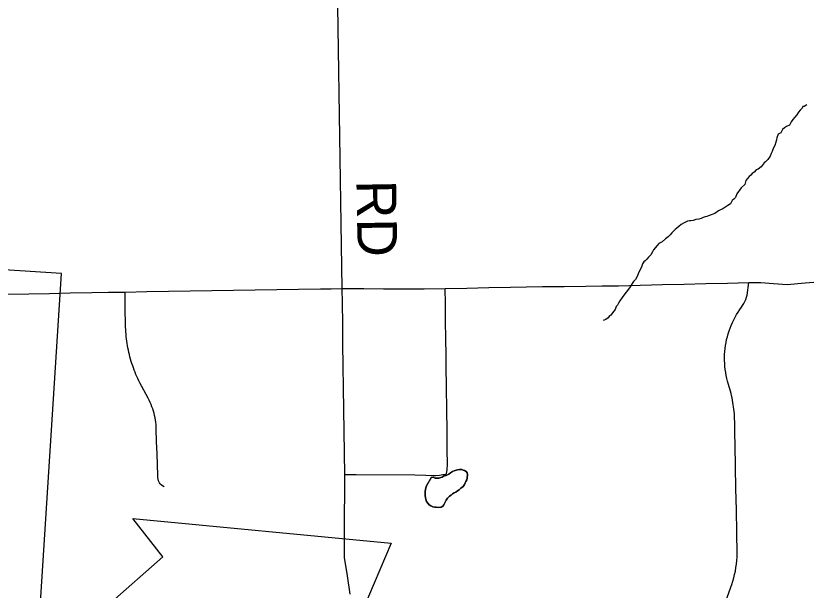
# Model space of a CAD drawing. Extents: x -11.4 to 84.1, y 11.1 to 59.
# Drawn here: x 29.384 to 30.516, y 44.72 to 45.542 of the extents above; entities that cross this region are included whole.
import ezdxf

# ---------------------------------------------------------------- set-up
doc = ezdxf.new("R2010")
doc.units = 0
for name, color, linetype in [('GM_X_Corporation', 7, 'Continuous'), ('GM_X_Minor_Lake', 7, 'Continuous'), ('GM_X_Minor_River', 7, 'Continuous'), ('GM_X_Township_Road', 7, 'Continuous'), ('GM_X_Township_Road_Text', 7, 'Continuous')]:
    doc.layers.add(name, color=color, linetype=linetype)

msp = doc.modelspace()

# ---------------------------------------------------------------- linework, layer by layer
at = {"layer": 'GM_X_Corporation'}
for points in [[(29.4173, 44.6657), (29.4494, 45.1735), (28.9418, 45.206), (28.9363, 45.0881), (28.8122, 45.094), (28.8061, 44.8928), (28.7167, 44.8942), (28.7171, 44.5971)], [(29.441, 44.6327), (29.5946, 44.7683), (29.5515, 44.8229), (29.9217, 44.7877), (29.8078, 44.5206)]]:
    msp.add_lwpolyline(points, dxfattribs=at)
at = {"layer": 'GM_X_Minor_Lake'}
for points in [[(29.9792, 44.8819), (29.9794, 44.8819), (29.9824, 44.8816), (29.9847, 44.8809), (29.9866, 44.8809), (29.9897, 44.8806), (29.9927, 44.8818), (29.9946, 44.8822), (29.9976, 44.8838), (30.0002, 44.8846), (30.004, 44.8865), (30.0066, 44.8881), (30.0093, 44.89), (30.0119, 44.8912), (30.0145, 44.892), (30.0164, 44.8928), (30.0195, 44.8933), (30.0225, 44.8929), (30.0244, 44.8922), (30.0263, 44.8915), (30.029, 44.8904), (30.0302, 44.8885), (30.031, 44.8858), (30.0303, 44.8805), (30.0296, 44.8782), (30.0285, 44.8759), (30.0274, 44.874), (30.0263, 44.8717), (30.0244, 44.8686), (30.0214, 44.8663), (30.0188, 44.864), (30.0166, 44.8624), (30.0139, 44.8608), (30.0117, 44.8597), (30.0094, 44.8581), (30.0072, 44.8565), (30.0049, 44.855), (30.0023, 44.8519), (30.0001, 44.8492), (29.9986, 44.8465), (29.9979, 44.8446), (29.9968, 44.8427), (29.9953, 44.8408), (29.993, 44.8392), (29.9888, 44.8388), (29.9858, 44.8391), (29.9839, 44.8394), (29.9812, 44.8398), (29.9785, 44.8412), (29.9759, 44.8427), (29.9739, 44.845), (29.972, 44.8472), (29.9712, 44.8506), (29.9708, 44.8525), (29.9703, 44.8559), (29.9703, 44.8578), (29.9702, 44.862), (29.9706, 44.8643), (29.9709, 44.867), (29.972, 44.8697), (29.9792, 44.8819)], [(30.0188, 44.864), (30.0214, 44.8663), (30.0244, 44.8686), (30.0263, 44.8717), (30.0274, 44.874), (30.0285, 44.8759), (30.0296, 44.8782), (30.0303, 44.8805), (30.031, 44.8858), (30.0302, 44.8885), (30.029, 44.8904), (30.0263, 44.8915), (30.0244, 44.8922), (30.0225, 44.8929), (30.0195, 44.8933), (30.0164, 44.8928), (30.0145, 44.892), (30.0119, 44.8912), (30.0093, 44.89), (30.0066, 44.8881), (30.004, 44.8865), (30.0002, 44.8846), (29.9976, 44.8838), (29.9946, 44.8822), (29.9927, 44.8818), (29.9897, 44.8806), (29.9866, 44.8809), (29.9847, 44.8809), (29.9824, 44.8816), (29.9794, 44.8819), (29.9792, 44.8819)], [(29.9792, 44.8819), (29.972, 44.8697), (29.9709, 44.867), (29.9706, 44.8643), (29.9702, 44.862), (29.9703, 44.8578), (29.9703, 44.8559), (29.9708, 44.8525), (29.9712, 44.8506), (29.972, 44.8472), (29.9739, 44.845), (29.9759, 44.8427), (29.9785, 44.8412), (29.9812, 44.8398), (29.9839, 44.8394), (29.9858, 44.8391), (29.9888, 44.8388), (29.993, 44.8392), (29.9953, 44.8408), (29.9968, 44.8427), (29.9979, 44.8446), (29.9986, 44.8465), (30.0001, 44.8492), (30.0023, 44.8519), (30.0049, 44.855), (30.0072, 44.8565), (30.0094, 44.8581), (30.0117, 44.8597), (30.0139, 44.8608), (30.0166, 44.8624), (30.0188, 44.864)]]:
    msp.add_lwpolyline(points, dxfattribs=at)
at = {"layer": 'GM_X_Minor_River'}
for points in [[(30.5166, 45.4148), (30.5128, 45.4124), (30.5106, 45.412), (30.5098, 45.4097), (30.5072, 45.407), (30.5046, 45.4039), (30.502, 45.4005), (30.4987, 45.3966), (30.4964, 45.3935), (30.4942, 45.3904)], [(30.4942, 45.3904), (30.4916, 45.3855), (30.4875, 45.3835), (30.4845, 45.3815), (30.4819, 45.3792), (30.4793, 45.3746), (30.4755, 45.3726), (30.4737, 45.3673), (30.473, 45.3646), (30.4723, 45.3612), (30.4705, 45.3562), (30.469, 45.3531), (30.4679, 45.3508), (30.4668, 45.3478), (30.4653, 45.3451), (30.4639, 45.3413), (30.4606, 45.3363), (30.4576, 45.3332), (30.4553, 45.3316), (30.4538, 45.3297), (30.4512, 45.3259), (30.4467, 45.3224), (30.4441, 45.3216), (30.4411, 45.3185), (30.4385, 45.3165), (30.4366, 45.3142), (30.434, 45.3119), (30.4292, 45.3065), (30.4277, 45.3008), (30.4225, 45.2961), (30.4203, 45.2926), (30.4188, 45.2907), (30.4162, 45.2873), (30.4144, 45.2819), (30.4118, 45.2796), (30.4095, 45.2776), (30.4073, 45.273), (30.4035, 45.2707), (30.4005, 45.2687), (30.3979, 45.2668), (30.3953, 45.2656), (30.393, 45.2644), (30.39, 45.2632), (30.3847, 45.2594), (30.3795, 45.2574), (30.3757, 45.2558), (30.3734, 45.255), (30.3712, 45.2542), (30.3681, 45.2534), (30.3651, 45.2522), (30.3617, 45.251), (30.3576, 45.2505), (30.3538, 45.2493), (30.3507, 45.2489), (30.3485, 45.2485), (30.3458, 45.2481), (30.3409, 45.2457), (30.3368, 45.2434), (30.3334, 45.2406), (30.3304, 45.2383), (30.3282, 45.2364), (30.3252, 45.2333), (30.3233, 45.2314), (30.3211, 45.2287), (30.3181, 45.2256), (30.314, 45.2228), (30.3095, 45.2186), (30.3046, 45.2162), (30.3023, 45.2135), (30.2971, 45.2073), (30.2957, 45.2043), (30.2931, 45.2001), (30.2901, 45.1966), (30.2875, 45.1939), (30.2849, 45.1916), (30.283, 45.19), (30.2815, 45.1873), (30.2797, 45.1823), (30.2771, 45.1774), (30.2749, 45.1731), (30.2738, 45.1693), (30.2713, 45.1647), (30.2683, 45.162), (30.2664, 45.1589), (30.2635, 45.1543), (30.2597, 45.1493), (30.256, 45.1443), (30.2523, 45.1389), (30.249, 45.1343), (30.2468, 45.1308), (30.2453, 45.1282), (30.2438, 45.1262), (30.242, 45.122), (30.2401, 45.1193), (30.2383, 45.117), (30.236, 45.1139), (30.2342, 45.1128), (30.2323, 45.1101), (30.2289, 45.1077), (30.2263, 45.1066), (30.2255, 45.1065)], [(30.2255, 45.1065), (30.2255, 45.1062), (30.2255, 45.1062)]]:
    msp.add_lwpolyline(points, dxfattribs=at)
at = {"layer": 'GM_X_Township_Road'}
for points in [[(29.863, 44.7149), (29.8589, 44.7411), (29.8548, 44.7674), (29.8549, 44.7984), (29.8549, 44.8295), (29.855, 44.8576), (29.8551, 44.8857), (29.8547, 44.9168), (29.8542, 44.9478), (29.8538, 44.9789), (29.8534, 45.01), (29.8529, 45.0411), (29.8525, 45.0721), (29.8521, 45.1015), (29.8517, 45.131), (29.8515, 45.1518), (29.851, 45.1829), (29.8506, 45.214), (29.8501, 45.245), (29.8496, 45.2761), (29.8491, 45.3071), (29.8486, 45.3382), (29.8482, 45.3693), (29.8477, 45.4003), (29.8472, 45.4314), (29.8467, 45.4625), (29.8462, 45.4935), (29.8458, 45.5246), (29.8453, 45.5556)], [(29.8515, 45.1518), (29.8826, 45.1517), (29.9103, 45.1515), (29.938, 45.1514), (29.9685, 45.1516), (29.999, 45.1519), (30.03, 45.1525), (30.0611, 45.1532), (30.0922, 45.1538), (30.1151, 45.1542), (30.138, 45.1547), (30.1691, 45.155), (30.2002, 45.1553), (30.2235, 45.1555), (30.2469, 45.1557), (30.2779, 45.1566), (30.294, 45.1571), (30.31, 45.1575), (30.3411, 45.1582), (30.3721, 45.159), (30.4028, 45.1597), (30.4335, 45.1604), (30.4508, 45.1607), (30.4686, 45.1592), (30.4884, 45.1576), (30.5142, 45.1602), (30.545, 45.1625)], [(30.4002, 44.7035), (30.4077, 44.725), (30.4091, 44.7288), (30.4106, 44.7335), (30.412, 44.7383), (30.4132, 44.7431), (30.4142, 44.7479), (30.4151, 44.7528), (30.4158, 44.7577), (30.4163, 44.7627), (30.4166, 44.7676), (30.4168, 44.7726), (30.4162, 44.8036), (30.4157, 44.8347), (30.4151, 44.8658), (30.4145, 44.8968), (30.414, 44.9279), (30.4137, 44.9444), (30.4134, 44.9609), (30.4132, 44.966), (30.4131, 44.9693), (30.4128, 44.9726), (30.4125, 44.9759), (30.4122, 44.9792), (30.4117, 44.9825), (30.4113, 44.9857), (30.4108, 44.989), (30.4102, 44.9923), (30.4096, 44.9955), (30.4088, 44.9987), (30.4081, 45.002), (30.4073, 45.0052), (30.4064, 45.0084), (30.4055, 45.0115), (30.4045, 45.0147), (30.4032, 45.0192), (30.4021, 45.0233), (30.4012, 45.0276), (30.4004, 45.0318), (30.3998, 45.036), (30.3993, 45.0403), (30.399, 45.0446), (30.3988, 45.0489), (30.3989, 45.0575), (30.3992, 45.0618), (30.3996, 45.0661), (30.4002, 45.0703), (30.4009, 45.0746), (30.4017, 45.0788), (30.4028, 45.0829), (30.4039, 45.0871), (30.4052, 45.0912), (30.4067, 45.0952), (30.4082, 45.0992), (30.4099, 45.1032), (30.4118, 45.1071), (30.4138, 45.1109), (30.4159, 45.1146), (30.4182, 45.1183), (30.4206, 45.1219), (30.4231, 45.1254), (30.4246, 45.1275), (30.4263, 45.1304), (30.4278, 45.1333), (30.4291, 45.1363), (30.4302, 45.1394), (30.4311, 45.1426), (30.4335, 45.1604)], [(29.3718, 45.1438), (29.4028, 45.1444), (29.4325, 45.1449), (29.4621, 45.1455), (29.4931, 45.146), (29.5168, 45.1465), (29.5405, 45.1469), (29.5716, 45.1474), (29.6026, 45.1479), (29.6337, 45.1484), (29.6648, 45.1489), (29.6958, 45.1494), (29.7269, 45.1498), (29.758, 45.1503), (29.789, 45.1508), (29.8201, 45.1513), (29.8358, 45.1516), (29.8515, 45.1518)], [(29.5965, 44.8681), (29.5943, 44.8697), (29.5924, 44.8711), (29.591, 44.8727), (29.5898, 44.8742), (29.5886, 44.8767), (29.5879, 44.8793), (29.5875, 44.8816), (29.5873, 44.8843), (29.5863, 44.9153), (29.5857, 44.9331), (29.5851, 44.9509), (29.5849, 44.9572), (29.5845, 44.9605), (29.5841, 44.9637), (29.5836, 44.967), (29.5829, 44.9702), (29.5821, 44.9735), (29.5812, 44.9766), (29.5802, 44.9798), (29.5791, 44.9829), (29.5779, 44.986), (29.5766, 44.989), (29.5752, 44.992), (29.5737, 44.9949), (29.5644, 45.0118), (29.5617, 45.017), (29.5603, 45.02), (29.5588, 45.023), (29.5575, 45.026), (29.5562, 45.029), (29.5549, 45.0321), (29.5537, 45.0352), (29.5525, 45.0383), (29.5515, 45.0414), (29.5504, 45.0445), (29.5494, 45.0477), (29.5485, 45.0509), (29.5476, 45.054), (29.5468, 45.0573), (29.5461, 45.0605), (29.5454, 45.0637), (29.5447, 45.0669), (29.5441, 45.0702), (29.5436, 45.0735), (29.5431, 45.0767), (29.5427, 45.08), (29.5423, 45.0833), (29.542, 45.0866), (29.5418, 45.0899), (29.5416, 45.0932), (29.5414, 45.0965), (29.5413, 45.0998), (29.5409, 45.1233), (29.5405, 45.1469)], [(30.0008, 44.8875), (30.0019, 44.8925), (30.0021, 44.9), (30.0019, 44.9218), (30.0015, 44.9481), (30.0012, 44.9791), (30.0008, 45.0102), (30.0004, 45.0413), (30.0001, 45.0593), (29.9999, 45.0773), (29.9995, 45.1084), (29.9993, 45.1301), (29.999, 45.1519)], [(29.8551, 44.8857), (29.8716, 44.886), (29.9554, 44.8854), (29.9711, 44.8849), (29.9811, 44.8845), (29.9854, 44.8847), (29.9906, 44.8852), (29.9955, 44.8857), (29.9994, 44.8861), (30.0008, 44.8875)]]:
    msp.add_lwpolyline(points, dxfattribs=at)

# ---------------------------------------------------------------- texts
at = {"layer": 'GM_X_Township_Road_Text'}
msp.add_text('RD', height=0.05682, rotation=270.9829, dxfattribs=at).set_placement((29.8717, 45.3065))

doc.saveas('drawing.dxf')
